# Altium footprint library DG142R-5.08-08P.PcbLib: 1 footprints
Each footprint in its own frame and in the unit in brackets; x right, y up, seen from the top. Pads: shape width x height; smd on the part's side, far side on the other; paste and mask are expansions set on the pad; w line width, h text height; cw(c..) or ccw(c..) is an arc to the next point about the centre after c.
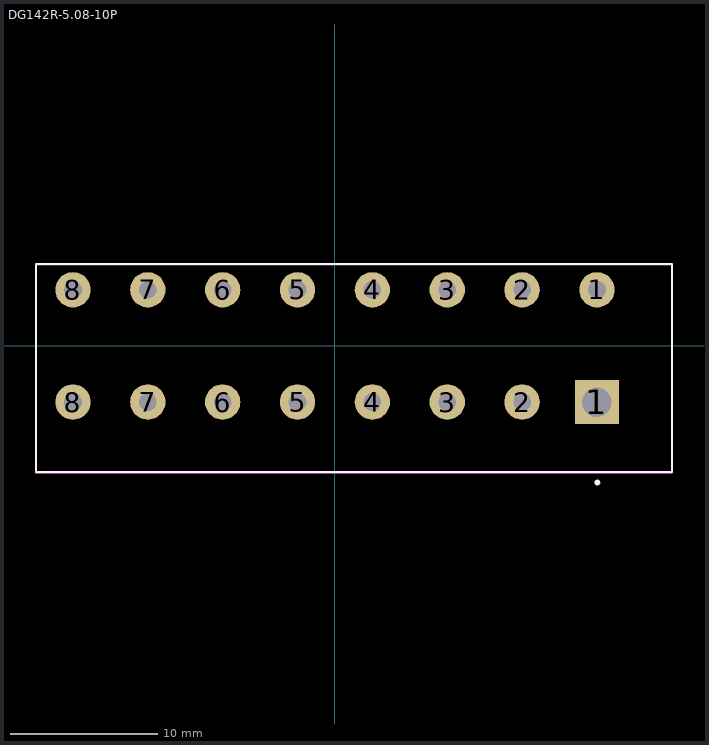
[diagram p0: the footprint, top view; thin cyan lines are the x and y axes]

## DG142R-5.08-10P [mm]
pads (16):
  rect 3x3 hole 2: 1(17.78,-3.81)
  round 2.4 hole 1.2: 1(17.78,3.81) 2(12.7,-3.81) 2(12.7,3.81) 3(7.62,-3.81) 3(7.62,3.81) 4(2.54,-3.81) 4(2.54,3.81) 5(-2.54,-3.81) 5(-2.54,3.81) 6(-7.62,-3.81) 6(-7.62,3.81) 7(-12.7,-3.81) 7(-12.7,3.81) 8(-17.78,-3.81) 8(-17.78,3.81)
Top Overlay:
  circle w0.2: c17.805,-9.271 r0.1
  lines w0.127: -20.295,-8.56 -20.295,5.563 22.885,5.563 22.885,-8.56 -20.295,-8.56
Mechanical 13:
  lines w0.127: -20.3,-8.611 -20.3,5.512 22.86,5.512 22.86,-8.611 -20.3,-8.611
3D body "DG142R-5.08-08P.stp": height 13.52, standoff -3.38, extent -20.32,-8.467 22.86,5.635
